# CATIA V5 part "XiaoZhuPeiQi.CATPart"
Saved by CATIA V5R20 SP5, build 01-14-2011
Part number: Part1
Bounding box of the stored display mesh (mm): x -40 to 30, y -150 to 150, z -149.807 to 180
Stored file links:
  E:\小猪佩奇\XiaoZhuPeiQi.CATPart
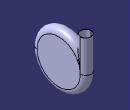
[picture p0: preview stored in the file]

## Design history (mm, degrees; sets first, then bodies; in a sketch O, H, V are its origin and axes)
Body1 (main body)
  Sketch1 on yz-plane, origin (0, 0, 0), H (0, 1, 0), V (0, 0, 1)
    circle A1 centre (0, 0) radius 150
    radius A1 = 150
  Pad1: profile Sketch1, direction (1, 0, 0), length 30
  Fillet1: radius 30, on edge [face of Pad1 from Sketch1.A1 | end face of Pad1]
  Shell1: ExtOffset 0, Face start face of Pad1, IntOffset 2
  Mirror1: of the body so far, about start face of Pad1
  Sketch2 on xy-plane, origin (0, 0, 0), H (1, 0, 0), V (0, 1, 0)
    circle A1 centre (0, 120) radius 30
    point P1 (0, 120)
    radius A1 = 30
    distance P1 H = 120
    coincidence: P1 V
  Pad2: profile Sketch2, direction (0, 0, 1), length 180
  Sketch3 on end face of Pad2, origin (0, 0, 180), H (1, 0, 0), V (0, 1, 0)
    circle A1 centre (0, 120) radius 29
    reference projected circle E1 centre (0, 120) radius 30 from edge [face of Pad2 from Sketch2.A1 | end face of Pad2]
    radius A1 = 29
    concentricity: E1 A1
  Pocket1: profile Sketch3, direction (0, 0, -1), length 180
  Sketch4 on face of Mirror1, origin (-30, 0, 0), H (0, -1, 0), V (0, 0, 1)
    circle A1 centre (0, 0) radius 75
    circle A2 centre (-30.1396, -107.5849) radius 25
    point P1 (-30.1396, -107.5849)
    radius A1 = 75
    distance P1 A2 = 25
  Pad3: profile Sketch4, direction (-1, 0, 0), length 5
  Sketch5 on face of Mirror1, origin (-30, 0, 0), H (0, -1, 0), V (0, 0, 1)
    spline S1 through (80, -30) (90, -10) (83.2412, 27.6124) (57.5749, 65.2903)
    offsetcurve C1
    construction line L1 (80, -30) -> (82.1355, -31.8413)
    point P3 (80, -30)
    construction line L2 through (80, -30) direction (-0.653, -0.7574)
    construction line L3 (57.5749, 65.2903) -> (59.5914, 67.2614)
    point P4 (57.5749, 65.2903)
    construction line L4 through (57.5749, 65.2903) direction (-0.699, 0.7151)
    line L5 (80, -30) -> (82.1355, -31.8413)
    point P5 (80, -30)
    line L6 (57.5749, 65.2903) -> (59.5914, 67.2614)
    point P6 (57.5749, 65.2903)
    point P7 (80, -30)
    point P8 (57.5749, 65.2903)
    coincidence: P7 P3, P8 P4, P7 P5, P8 P6
    tangency: L2 S1, L4 S1
    perpendicularity: L1 L2, L3 L4
  Pad4: profile Sketch5, direction (-1, 0, 0), length 5
  Sketch6 on end face of Pad3, origin (-35, 0, 0), H (0, -1, 0), V (0, 0, 1)
    polyline C1
    polyline C2
    polyline C3
    polyline C4
    polyline C5
    polyline C6
    polyline C7
    polyline C8
    polyline C9
    polyline C10
    polyline C11
    polyline C12
    polyline C13
    polyline C14
    polyline C15
    polyline C16
    polyline C17
    polyline C18
    polyline C19
    polyline C20
    polyline C21
    polyline C22
    polyline C23
    polyline C24
    polyline C25
    polyline C26
    polyline C27
    polyline C28
    polyline C29
    polyline C30
    polyline C31
    polyline C32
    polyline C33
    polyline C34
  Pad5: profile Sketch6, direction (-1, 0, 0), length 5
